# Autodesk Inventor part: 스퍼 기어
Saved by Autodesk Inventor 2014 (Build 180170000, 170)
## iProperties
Created: 2026-06
Part Number: 스퍼 기어
Material: 강철, 합금
Document SubType Name: Modeling
Designer: dg
Density: 7.85 g/cm^3
Appearance: 반연마
Mass: 304.158 g
Surface Area: 153.576 cm^2
Volume: 38.7463 cm^3
Author: jhkim
Creation Date: 2026-05-29
Sending System: Autodesk Inventor 2027
Preprocessor: ST-DEVELOPER v20.1
Author: dg
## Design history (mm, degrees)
node "스퍼 기어1"
node "솔리드1"
node "기준1"
